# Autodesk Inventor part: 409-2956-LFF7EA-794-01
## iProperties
Shininess: 64.0
Angle Display Precision: 2
Document Length Units: 11272
Document Angle Units: 11279
Document Time Units: 11290
Document Mass Units: 11286
Document Length Units Precision: 3
Document Angle Units Precision: 2
Compacted: True
Created: 2002-04
Part Number: 409-2956-LFF7EA-794-01
Description: 2" PIPE MOUNT ANGLE
Document SubType Name: Modeling
Designer: S. Boerckel
Mass: 2540.04 g
Surface Area: 1040.68 cm^2
Volume: 316.319 cm^3
Density: 8.03 g/cm^3
Cost Center: 3 x 3 x 1/4 ANGLE
Material: STAINLESS STEEL, 304
Engineer: S. Boerckel
Density: 0.0
Volumn: 0.0
Area: 0.0
PropertySet Name: Model Information
Control State: 0
Master: False
Checked Out: False
length: 13.500 in
SMR: =<COST CENTER> - <MATERIAL>
Author: S. Boerckel
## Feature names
1. Extrusion1
2. Hole1
